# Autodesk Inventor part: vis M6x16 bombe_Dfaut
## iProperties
Created: 2006-03
Part Number: vis M6x16 bombe_Dfaut
Document SubType Name: Modeling
Designer: Flavien MARTY
Author: Flavien MARTY
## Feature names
1. Base1
